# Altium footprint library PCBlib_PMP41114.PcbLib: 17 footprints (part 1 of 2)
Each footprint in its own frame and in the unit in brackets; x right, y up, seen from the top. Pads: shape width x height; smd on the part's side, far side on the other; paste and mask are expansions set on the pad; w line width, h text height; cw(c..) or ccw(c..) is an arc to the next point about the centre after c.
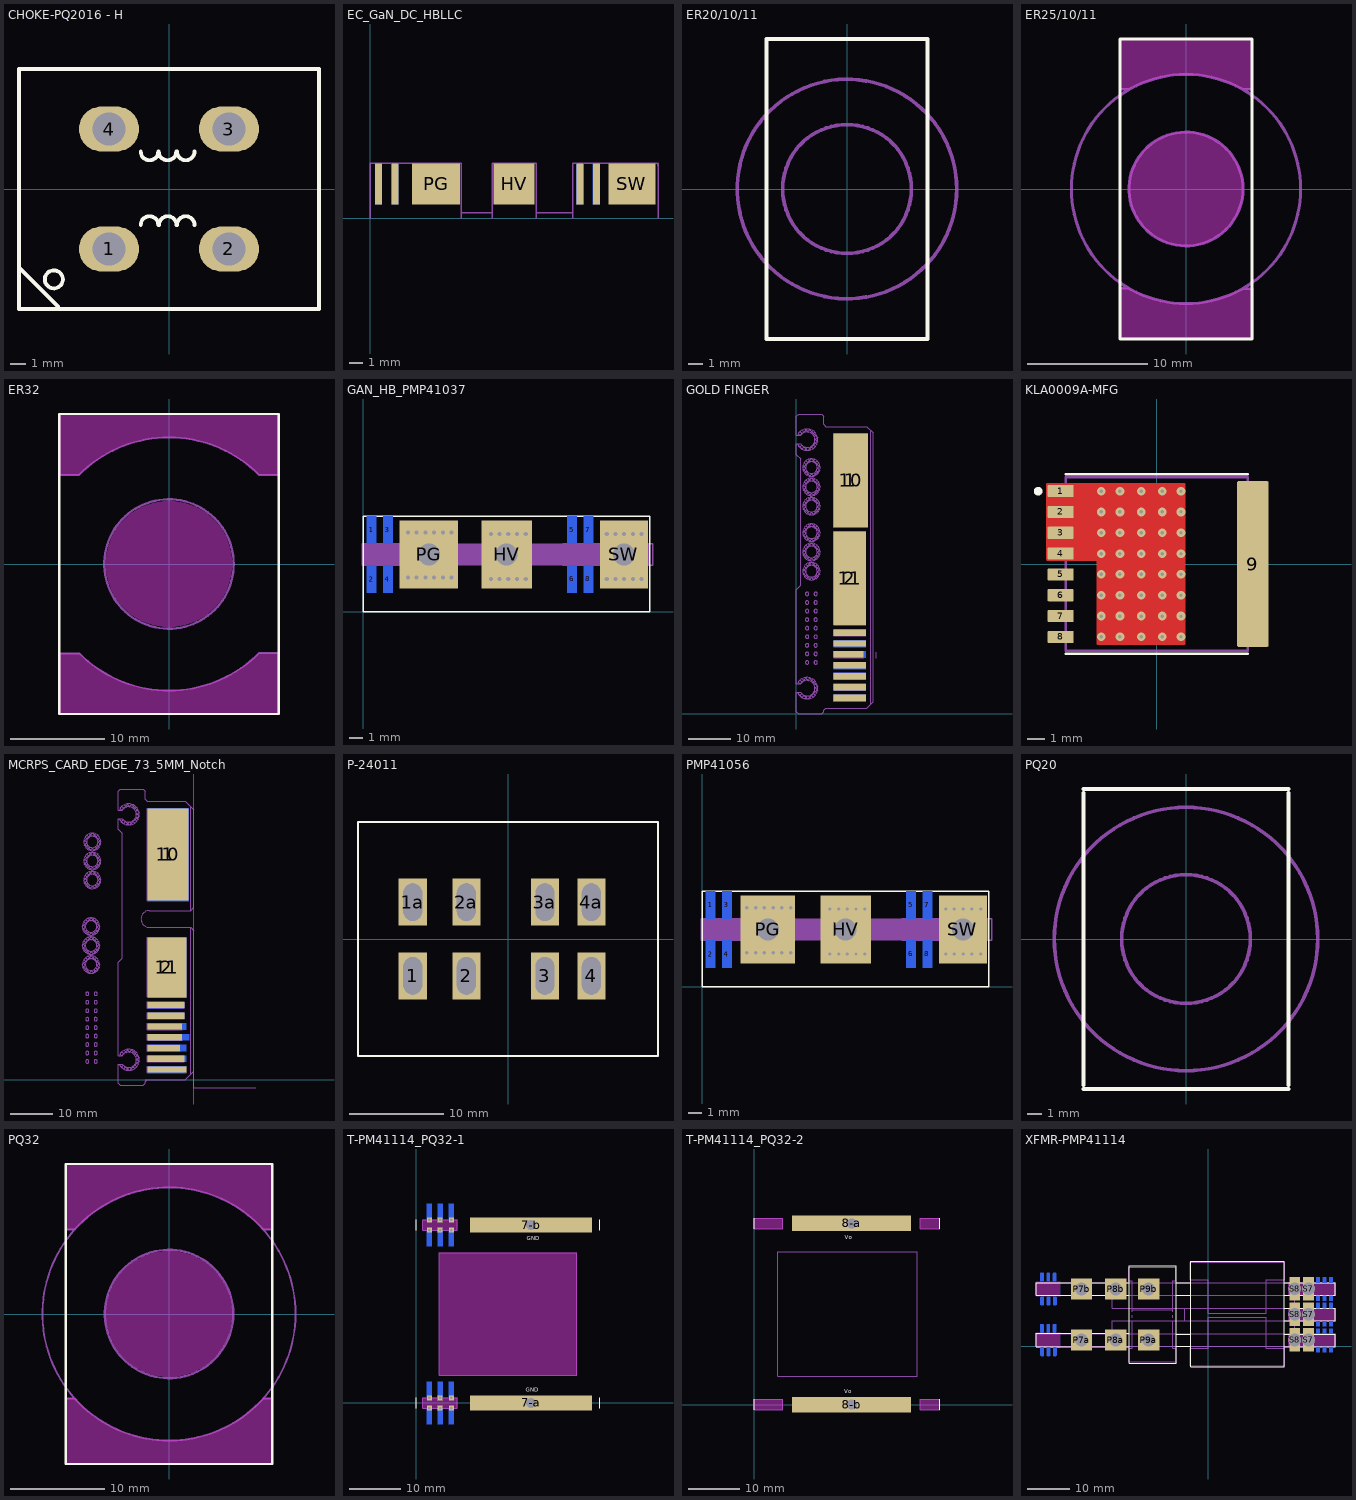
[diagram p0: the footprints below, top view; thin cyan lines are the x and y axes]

## CHOKE-PQ2016 - H [mm]
pads (4):
  oval 4x3 hole 2.2: 1(-4,-4) 2(4,-4) 3(4,4) 4(-4,4)
Top Overlay:
  circle w0.254: c-7.677,-6.026 r0.6
  lines w0.254: -10,-8 10,-8 ; -10,8 10,8 ; -9.906,-5.334 -7.406,-7.834 ; -1.883,-2.4 cw(c-1.3,-2.4) -0.717,-2.4 ; -1.883,2.5 ccw(c-1.3,2.5) -0.717,2.5 ; -0.683,2.5 ccw(c-0.1,2.5) 0.483,2.5 ; -0.666,-2.4 cw(c-0.083,-2.4) 0.5,-2.4 ; 0.534,-2.4 cw(c1.117,-2.4) 1.7,-2.4 ; 0.534,2.5 ccw(c1.117,2.5) 1.7,2.5
  lines w0.3: -10,-8 -10,8 ; 10,-8 10,8

## EC_GaN_DC_HBLLC [mm] "Edge connector of HB LLC GaN DC"
height 0.7
pads (11):
  rect 0.5x3 smd: 1(0.6,2.5) 3(1.8,2.5) 5(15.3,2.5) 7(16.5,2.5)
  rect 0.5x3 smd far side: 2(0.6,2.5) 4(1.8,2.5) 6(15.3,2.5) 8(16.5,2.5)
  rect 3x3 all layers, no hole: HV(10.5,2.5)
  rect 3.5x3 all layers, no hole: PG(4.8,2.5)
  rect 3.4x3 all layers, no hole: SW(19.1,2.5)
Mechanical 1:
  lines w0.1: -0.005,4 6.649,4 6.649,0.4 8.91,0.4 8.91,4 12.11,4 12.11,0.4 14.777,0.4 14.777,4 20.995,4 20.995,3.835
Mechanical 12:
  lines w0.1: 0,0 0,4 6.649,4 6.649,0 ; 8.9,0 8.9,4 12.1,4 12.1,0 ; 14.787,0 14.787,4 21,4 21,0

## ER20/10/11 [mm]
Top Overlay:
  lines w0.254: -5.5,-10.25 5.5,-10.25 5.5,10.25 -5.5,10.25 -5.5,-10.25
Mechanical 15:
  circle w0.254: c0,0 r4.4
  circle w0.254: c0,0 r7.5

## ER25/10/11 [mm] "Core"
Top Overlay:
  lines w0.254: -5.5,-12.5 -5.5,12.5 5.5,12.5 5.5,-12.5 -5.5,-12.5
Keep-Out Layer:
  board cut-out: -5.5,8.3 -4.714,8.3 -4.714,8.306 -4.352,8.501 -3.604,8.844 -2.83,9.121 -2.035,9.331 -1.224,9.471 -0.405,9.541 0.417,9.541 1.236,9.47 2.047,9.328 2.842,9.117 3.615,8.839 4.362,8.495 4.724,8.3 4.8,8.3 5.5,8.3 5.5,12.5 -5.5,12.5
  board cut-out: -5.493,-12.493 5.531,-12.493 5.531,-8.297 4.728,-8.297 4.363,-8.495 3.609,-8.842 2.828,-9.122 2.025,-9.333 1.207,-9.473 0.379,-9.542 -0.451,-9.539 -1.277,-9.464 -2.094,-9.317 -2.896,-9.1 -3.675,-8.815 -4.427,-8.462 -4.79,-8.262 -4.8,-8.278 -5.493,-8.278
  board cut-out: 0,-4.75 -0.311,-4.75 -0.929,-4.669 -1.53,-4.508 -2.105,-4.269 -2.645,-3.958 -3.139,-3.579 -3.579,-3.139 -3.958,-2.645 -4.269,-2.105 -4.508,-1.53 -4.669,-0.929 -4.75,-0.311 -4.75,0 -4.75,0.311 -4.669,0.929 -4.508,1.53 -4.269,2.105 -3.958,2.645 -3.579,3.139 -3.139,3.579 -2.645,3.958 -2.105,4.269 -1.53,4.508 -0.929,4.669 -0.311,4.75 0,4.75 0.311,4.75 0.929,4.669 1.53,4.508 2.105,4.269 2.645,3.958 3.139,3.579 3.579,3.139 3.958,2.645 4.269,2.105 4.508,1.53 4.669,0.929 4.75,0.311 4.75,0 4.75,-0.311 4.669,-0.929 4.508,-1.53 4.269,-2.105 3.958,-2.645 3.579,-3.139 3.139,-3.579 2.645,-3.958 2.105,-4.269 1.53,-4.508 0.929,-4.669 0.311,-4.75
Mechanical 2:
  circle w0.254: c0,0 r9.55
  circle w0.254: c0,0 r4.75
  lines w0.2: -5.5,-8.278 -4.8,-8.278 ; -5.493,-8.278 -5.493,-12.493 5.531,-12.493 5.531,-8.297 ; -4.79,-8.262 ccw(c0,0) 4.728,-8.297 5.5,-8.297 ; -4.714,8.3 -5.5,8.3 -5.5,12.5 5.5,12.5 5.5,8.3 4.8,8.3 ; -4.714,8.306 cw(c0,0) 4.724,8.3
3D body: height 0.25, standoff 0, extent -5.5,-12.5 5.5,12.5

## ER32 [mm] "Compatible to PQ32"
Top Overlay:
  lines w0.254: -11.7,-16 11.7,-16 11.7,16 -11.7,16 -11.7,-16
Keep-Out Layer:
  board cut-out: 0,-6.725 -0.33,-6.725 -0.988,-6.66 -1.636,-6.531 -2.268,-6.34 -2.879,-6.087 -3.462,-5.775 -4.011,-5.408 -4.522,-4.989 -4.989,-4.522 -5.408,-4.011 -5.775,-3.462 -6.087,-2.879 -6.34,-2.268 -6.531,-1.636 -6.66,-0.988 -6.725,-0.33 -6.725,0 -6.725,0.33 -6.66,0.988 -6.531,1.636 -6.34,2.268 -6.087,2.879 -5.775,3.462 -5.408,4.011 -4.989,4.522 -4.522,4.989 -4.011,5.408 -3.462,5.775 -2.879,6.087 -2.268,6.34 -1.636,6.531 -0.988,6.66 -0.33,6.725 0,6.725 0.33,6.725 0.988,6.66 1.636,6.531 2.268,6.34 2.879,6.087 3.462,5.775 4.011,5.408 4.522,4.989 4.989,4.522 5.408,4.011 5.775,3.462 6.087,2.879 6.34,2.268 6.531,1.636 6.66,0.988 6.725,0.33 6.725,0 6.725,-0.33 6.66,-0.988 6.531,-1.636 6.34,-2.268 6.087,-2.879 5.775,-3.462 5.408,-4.011 4.989,-4.522 4.522,-4.989 4.011,-5.408 3.462,-5.775 2.879,-6.087 2.268,-6.34 1.636,-6.531 0.988,-6.66 0.33,-6.725
  board cut-out: -11.7,9.5 -9.6,9.5 -9.596,9.496 -9.213,9.868 -8.405,10.564 -7.544,11.195 -6.636,11.756 -5.687,12.244 -4.702,12.655 -3.688,12.986 -2.651,13.237 -1.597,13.405 -0.534,13.489 0.534,13.489 1.597,13.405 2.651,13.237 3.688,12.986 4.702,12.655 5.687,12.244 6.636,11.756 7.544,11.195 8.405,10.564 9.213,9.868 9.596,9.496 9.6,9.5 11.7,9.5 11.7,16 -11.7,16
  board cut-out: -11.7,-16 -11.7,-9.542 -9.6,-9.542 -9.575,-9.517 -9.192,-9.888 -8.383,-10.582 -7.522,-11.21 -6.615,-11.768 -5.666,-12.253 -4.682,-12.662 -3.669,-12.992 -2.633,-13.241 -1.58,-13.407 -0.518,-13.49 0.548,-13.489 1.61,-13.404 2.662,-13.235 3.698,-12.984 4.71,-12.652 5.693,-12.241 6.641,-11.754 7.547,-11.193 8.407,-10.563 9.214,-9.867 9.596,-9.496 9.6,-9.5 11.7,-9.5 11.7,-16
Mechanical 2:
  circle w0.254: c0,0 r6.9
  lines w0.2: -9.6,-9.542 -11.7,-9.542 -11.7,-16 11.7,-16 11.7,-9.5 9.6,-9.5 ; -9.6,9.5 -11.7,9.5 -11.7,16 11.7,16 11.7,9.5 9.6,9.5 ; -9.596,9.496 cw(c0,0) 9.596,9.496 ; -9.575,-9.517 ccw(c0,0) 9.596,-9.496
3D body: height 0.25, standoff 0, extent -11.048,-15.968 11,16

## GAN_HB_PMP41037 [mm]
height 32
pads (11):
  rect 0.7x2 smd far side: 1(0.6,6) 2(0.6,2.4) 3(1.8,6) 4(1.8,2.4) 5(15.3,6) 6(15.3,2.4) 7(16.5,6) 8(16.5,2.4)
  rect 3.7x5 hole 1.6 square: HV(10.5,4.2)
  rect 4.3x5 hole 1.6 square: PG(4.8,4.2)
  rect 3.5x5 hole 1.6 square: SW(19.1,4.2)
via 3.9,2.5 diameter 0.5 hole 0.3
via 4.54,2.5 diameter 0.5 hole 0.3
via 5.18,2.5 diameter 0.5 hole 0.3
via 5.82,2.5 diameter 0.5 hole 0.3
via 6.46,2.5 diameter 0.5 hole 0.3
via 6.46,5.8 diameter 0.5 hole 0.3
via 5.82,5.8 diameter 0.5 hole 0.3
via 5.18,5.8 diameter 0.5 hole 0.3
via 4.54,5.8 diameter 0.5 hole 0.3
via 3.9,5.8 diameter 0.5 hole 0.3
via 9.34,2.4 diameter 0.5 hole 0.3
via 9.98,2.4 diameter 0.5 hole 0.3
via 10.62,2.4 diameter 0.5 hole 0.3
via 11.26,2.4 diameter 0.5 hole 0.3
via 11.9,2.4 diameter 0.5 hole 0.3
via 11.9,5.7 diameter 0.5 hole 0.3
via 11.26,5.7 diameter 0.5 hole 0.3
via 10.62,5.7 diameter 0.5 hole 0.3
via 9.98,5.7 diameter 0.5 hole 0.3
via 9.34,5.7 diameter 0.5 hole 0.3
via 17.84,2.4 diameter 0.5 hole 0.3
via 18.48,2.4 diameter 0.5 hole 0.3
via 19.12,2.4 diameter 0.5 hole 0.3
via 19.76,2.4 diameter 0.5 hole 0.3
via 20.4,2.4 diameter 0.5 hole 0.3
via 20.4,5.7 diameter 0.5 hole 0.3
via 19.76,5.7 diameter 0.5 hole 0.3
via 19.12,5.7 diameter 0.5 hole 0.3
via 18.48,5.7 diameter 0.5 hole 0.3
via 17.84,5.7 diameter 0.5 hole 0.3
via 3.26,5.8 diameter 0.5 hole 0.3
via 3.26,2.5 diameter 0.5 hole 0.3
Top Overlay:
  lines w0.1: 0,0 21,0 21,7 0,7 0,0
Mechanical 1:
  lines w0.1: -0.1,3.4 -0.1,5 6.8,5 6.8,3.4 -0.1,3.4 ; 8.763,3.4 12.246,3.4 12.246,5 8.763,5 8.763,3.4 ; 14.6,3.4 14.6,5 21.2,5 21.2,3.4 14.6,3.4
Mechanical 2:
  rectangle: 0,3.4 21,5
3D body: height 32, standoff 0, extent -0.1,3.4 21.2,5

## GOLD FINGER [mm]
pads (18):
  rect 8x21.83 smd: 1(12.748,54.51)
  rect 7.5x21.82 smd: 2(12.498,31.65)
  rect 7.5x1.5 smd: 3(12.498,18.96) 4(12.498,16.42) 6(12.498,11.34) 7(12.498,8.8) 8(12.498,6.26) 9(12.498,3.72)
  rect 7x1.5 smd: 5(12.248,13.88)
  rect 8x21.83 smd far side: 10(12.748,54.51)
  rect 7.5x21.82 smd far side: 11(12.498,31.65)
  rect 7.5x1.5 smd far side: 12(12.498,18.96) 13(12.498,16.42) 14(12.498,13.88) 15(12.498,11.34) 16(12.498,8.8) 17(12.498,6.26) 18(12.498,3.72)
Mechanical 16:
  drawing of 327 lines, arcs and shapes, not listed

## KLA0009A-MFG [mm]
height 16
pads (9):
  rrect14% 1.5x0.7 smd paste+0 mask-1000: 1(-5.539,4.2) 2(-5.539,3) 3(-5.539,1.8) 4(-5.539,0.6) 5(-5.539,-0.6) 6(-5.539,-1.8) 7(-5.539,-3) 8(-5.539,-4.2)
  rrect15% 1.843x9.6 smd paste-1000 mask-1000: 9(5.539,0)
via -3.208,4.2 diameter 0.5 hole 0.2
via -3.208,3 diameter 0.5 hole 0.2
via -3.208,1.8 diameter 0.5 hole 0.2
via -3.208,0.6 diameter 0.5 hole 0.2
via -3.208,-0.6 diameter 0.5 hole 0.2
via -3.208,-1.8 diameter 0.5 hole 0.2
via -3.208,-3 diameter 0.5 hole 0.2
via -3.208,-4.2 diameter 0.5 hole 0.2
via -2.12,4.2 diameter 0.5 hole 0.2
via -2.12,3 diameter 0.5 hole 0.2
via -2.12,1.8 diameter 0.5 hole 0.2
via -2.12,0.6 diameter 0.5 hole 0.2
via -2.12,-0.6 diameter 0.5 hole 0.2
via -2.12,-1.8 diameter 0.5 hole 0.2
via -2.12,-3 diameter 0.5 hole 0.2
via -2.12,-4.2 diameter 0.5 hole 0.2
via -0.9,4.2 diameter 0.5 hole 0.2
via -0.9,3 diameter 0.5 hole 0.2
via -0.9,1.8 diameter 0.5 hole 0.2
via -0.9,0.6 diameter 0.5 hole 0.2
via -0.9,-0.6 diameter 0.5 hole 0.2
via -0.9,-1.8 diameter 0.5 hole 0.2
via -0.9,-3 diameter 0.5 hole 0.2
via -0.9,-4.2 diameter 0.5 hole 0.2
via 0.32,4.2 diameter 0.5 hole 0.2
via 0.32,3 diameter 0.5 hole 0.2
via 0.32,1.8 diameter 0.5 hole 0.2
via 0.32,0.6 diameter 0.5 hole 0.2
via 0.32,-0.6 diameter 0.5 hole 0.2
via 0.32,-1.8 diameter 0.5 hole 0.2
via 0.32,-3 diameter 0.5 hole 0.2
via 0.32,-4.2 diameter 0.5 hole 0.2
via 1.4,4.2 diameter 0.5 hole 0.2
via 1.4,3 diameter 0.5 hole 0.2
via 1.4,1.8 diameter 0.5 hole 0.2
via 1.4,0.6 diameter 0.5 hole 0.2
via 1.4,-0.6 diameter 0.5 hole 0.2
via 1.4,-1.8 diameter 0.5 hole 0.2
via 1.4,-3 diameter 0.5 hole 0.2
via 1.4,-4.2 diameter 0.5 hole 0.2
Top Layer:
  region: -6.36,4.6 -6.36,4.614 -6.349,4.64 -6.33,4.659 -6.304,4.67 -6.29,4.67 1.587,4.67 1.601,4.67 1.627,4.659 1.646,4.64 1.657,4.614 1.657,4.6 1.657,-4.6 1.657,-4.614 1.646,-4.64 1.627,-4.659 1.601,-4.67 1.587,-4.67 -3.388,-4.67 -3.402,-4.67 -3.428,-4.659 -3.447,-4.64 -3.458,-4.614 -3.458,-4.6 -3.458,0.13 -3.459,0.14 -3.466,0.158 -3.48,0.172 -3.498,0.179 -3.508,0.18 -6.29,0.18 -6.304,0.18 -6.33,0.191 -6.349,0.21 -6.36,0.236 -6.36,0.25
Top Overlay:
  circle w0.25: c-6.837,4.197 r0.125
  lines w0.15: -5.24,-5.175 5.24,-5.175 ; -5.24,5.175 5.24,5.175
Top Paste:
  drawing of 40 lines, arcs and shapes, not listed
Top Solder:
  drawing of 6 lines, arcs and shapes, not listed
Mechanical 5:
  lines w0.15: -5.24,-5 -5.24,5 5.24,5 5.24,-5 -5.24,-5
  text ".Designator" at 0.733,-0.083 h0.5
3D body "IC_LMG365x_TO-9.STEP": height 0.25, standoff 0, extent -6.46,-5.1 6.56,5.1

## MCRPS_CARD_EDGE_73_5MM_Notch [mm] "Edge Connector with golden finger"
pads (18):
  rect 9.75x21.83 smd: 1(-6.1,53.2)
  rect 9.25x14.2 smd: 2(-6.369,26.52)
  rect 8.75x1.5 smd: 3(-6.625,17.63) 4(-6.625,15.09) 8(-6.625,4.93)
  rect 8.25x1.5 smd: 5(-6.875,12.55) 6(-6.875,10.01)
  rect 7.75x1.5 smd: 7(-7.125,7.47)
  rect 9.25x1.5 smd: 9(-6.375,2.39)
  rect 9.75x21.83 smd far side: 10(-6.125,53.19)
  rect 9.25x14.2 smd far side: 11(-6.375,26.52)
  rect 8.75x1.5 smd far side: 12(-6.625,17.63) 13(-6.625,15.09) 18(-6.625,2.39)
  rect 9.25x1.5 smd far side: 14(-6.375,12.55) 16(-6.375,7.47) 17(-6.375,4.93)
  rect 9.9x1.5 smd far side: 15(-6.05,10.01)
Mechanical 10:
  lines w0.025: 0,2 0,-1.9 14.6,-1.9
  text "30u in GOLD  /100u in NICKEL" at 1.648,16.052 h0.76
  text "2x 0.77mm, 2x 30 deg" at 1.452,-1.494 h0.76
Mechanical 15:
  drawing of 329 lines, arcs and shapes, not listed
Mechanical 16:
  drawing of 325 lines, arcs and shapes, not listed

## P-24011 [mm] "LLC transformer from Cyntec"
pads (8):
  rect 3x5 hole 2 slot 4 at 90 deg: 1(-10.16,-3.937) 1a(-10.16,3.937) 2(-4.445,-3.937) 2a(-4.445,3.937) 3(3.937,-3.937) 3a(3.937,3.937) 4(8.89,-3.937) 4a(8.89,3.937)
Top Overlay:
  lines w0.2: -16,-12.5 -16,12.5 16,12.5 16,-12.5 -16,-12.5

## PMP41056 [mm] "GaN board Interface"
height 32
pads (11):
  rect 0.7x2 smd far side: 1(0.6,6) 2(0.6,2.4) 3(1.8,6) 4(1.8,2.4) 5(15.3,6) 6(15.3,2.4) 7(16.5,6) 8(16.5,2.4)
  rect 3.7x5 hole 1.6 square: HV(10.5,4.2)
  rect 4x5 hole 1.6 square: PG(4.8,4.2)
  rect 3.5x5 hole 1.6 square: SW(19.1,4.2)
via 3.26,2.5 diameter 0.5 hole 0.254
via 3.26,5.8 diameter 0.5 hole 0.254
via 17.84,5.7 diameter 0.5 hole 0.254
via 18.48,5.7 diameter 0.5 hole 0.254
via 19.12,5.7 diameter 0.5 hole 0.254
via 19.76,5.7 diameter 0.5 hole 0.254
via 20.4,5.7 diameter 0.5 hole 0.254
via 20.4,2.4 diameter 0.5 hole 0.254
via 19.76,2.4 diameter 0.5 hole 0.254
via 19.12,2.4 diameter 0.5 hole 0.254
via 18.48,2.4 diameter 0.5 hole 0.254
via 17.84,2.4 diameter 0.5 hole 0.254
via 9.34,5.7 diameter 0.5 hole 0.254
via 9.98,5.7 diameter 0.5 hole 0.254
via 10.62,5.7 diameter 0.5 hole 0.254
via 11.26,5.7 diameter 0.5 hole 0.254
via 11.9,5.7 diameter 0.5 hole 0.254
via 11.9,2.4 diameter 0.5 hole 0.254
via 11.26,2.4 diameter 0.5 hole 0.254
via 10.62,2.4 diameter 0.5 hole 0.254
via 9.98,2.4 diameter 0.5 hole 0.254
via 9.34,2.4 diameter 0.5 hole 0.254
via 3.9,5.8 diameter 0.5 hole 0.254
via 4.54,5.8 diameter 0.5 hole 0.254
via 5.18,5.8 diameter 0.5 hole 0.254
via 5.82,5.8 diameter 0.5 hole 0.254
via 6.46,5.8 diameter 0.5 hole 0.254
via 6.46,2.5 diameter 0.5 hole 0.254
via 5.82,2.5 diameter 0.5 hole 0.254
via 5.18,2.5 diameter 0.5 hole 0.254
via 4.54,2.5 diameter 0.5 hole 0.254
via 3.9,2.5 diameter 0.5 hole 0.254
Top Overlay:
  lines w0.1: 0,0 0,7 21,7 21,0 0,0
Mechanical 1:
  lines w0.1: -0.1,3.4 6.8,3.4 6.8,5 -0.1,5 -0.1,3.4 ; 8.763,3.4 8.763,5 12.246,5 12.246,3.4 8.763,3.4 ; 14.6,3.4 21.2,3.4 21.2,5 14.6,5 14.6,3.4
Mechanical 2:
  rectangle: 0,3.4 21,5

## PQ20 [mm] "Core"
Top Overlay:
  lines w0.254: -7,-10.25 7,-10.25 ; -7,-10 -7,10 ; -7,10.25 7,10.25 ; 7,-10 7,10
Mechanical 2:
  circle w0.254: c0,0 r4.4
  circle w0.254: c0,0 r9

## PQ32 [mm] "Core"
Top Overlay:
  lines w0.254: -11,-16 11,-16 11,16 -11,16 -11,-16
Keep-Out Layer:
  board cut-out: 0,-6.725 -0.33,-6.725 -0.988,-6.66 -1.636,-6.531 -2.268,-6.34 -2.879,-6.087 -3.462,-5.775 -4.011,-5.408 -4.522,-4.989 -4.989,-4.522 -5.408,-4.011 -5.775,-3.462 -6.087,-2.879 -6.34,-2.268 -6.531,-1.636 -6.66,-0.988 -6.725,-0.33 -6.725,0 -6.725,0.33 -6.66,0.988 -6.531,1.636 -6.34,2.268 -6.087,2.879 -5.775,3.462 -5.408,4.011 -4.989,4.522 -4.522,4.989 -4.011,5.408 -3.462,5.775 -2.879,6.087 -2.268,6.34 -1.636,6.531 -0.988,6.66 -0.33,6.725 0,6.725 0.33,6.725 0.988,6.66 1.636,6.531 2.268,6.34 2.879,6.087 3.462,5.775 4.011,5.408 4.522,4.989 4.989,4.522 5.408,4.011 5.775,3.462 6.087,2.879 6.34,2.268 6.531,1.636 6.66,0.988 6.725,0.33 6.725,0 6.725,-0.33 6.66,-0.988 6.531,-1.636 6.34,-2.268 6.087,-2.879 5.775,-3.462 5.408,-4.011 4.989,-4.522 4.522,-4.989 4.011,-5.408 3.462,-5.775 2.879,-6.087 2.268,-6.34 1.636,-6.531 0.988,-6.66 0.33,-6.725
  board cut-out: -11,-16 -11,-9 -10.062,-9 -9.676,-9.415 -8.851,-10.193 -7.965,-10.9 -7.022,-11.53 -6.03,-12.079 -4.995,-12.542 -3.925,-12.917 -2.827,-13.201 -1.71,-13.391 -0.58,-13.488 0.554,-13.489 1.684,-13.395 2.802,-13.206 3.9,-12.924 4.971,-12.552 6.006,-12.09 7,-11.544 7.943,-10.916 8.831,-10.211 9.657,-9.434 10.045,-9.02 10.045,-9 11,-9 11,-16
  board cut-out: -11,9 -11,16 11,16 11,9 10.045,9 10.062,9 9.676,9.415 8.851,10.193 7.965,10.9 7.022,11.53 6.03,12.079 4.995,12.542 3.925,12.917 2.827,13.201 1.71,13.391 0.58,13.488 -0.554,13.489 -1.684,13.395 -2.802,13.206 -3.9,12.924 -4.971,12.552 -6.006,12.09 -7,11.544 -7.943,10.916 -8.831,10.211 -9.657,9.434 -10.045,9.02 -10.045,9
Mechanical 2:
  circle w0.2: c0,0 r13.5
  circle w0.254: c0,0 r6.85
  lines w0.2: -10.045,9 -11,9 -11,16 11,16 11,9 10.045,9 ; -10.045,9.02 cw(c0,0) 10.062,9 ; 10.045,-9.02 cw(c0,0) -10.062,-9 -11,-9 -11,-16 11,-16 11,-9 10.045,-9
3D body: height 0.25, standoff 0, extent -11.048,-15.968 11,16

## T-PM41114_PQ32-1 [mm] "Customized to Sunlord"
pads (26):
  rect 1x3 smd far side: 1-a(2.545,-2.7) 1-b(2.545,32.3) 2-a(4.65,-2.7) 2-b(4.65,32.3) 3-a(6.85,-2.7) 3-b(6.85,32.3) 4-a(2.545,2.7) 4-b(2.545,37.7) 5-a(4.65,2.7) 5-b(4.65,37.7) 6-a(6.85,2.7) 6-b(6.85,37.7)
  rect 1x1 hole 0.5: 1-a(2.545,-1) 1-b(2.545,34) 2-a(4.65,-1) 2-b(4.65,34) 3-a(6.85,-1) 3-b(6.85,34) 4-a(2.545,1) 4-b(2.545,36) 5-a(4.65,1) 5-b(4.65,36) 6-a(6.85,1) 6-b(6.85,36)
  rect 24x3 hole 2 square: 7-a(22.55,0) 7-b(22.55,35)
Top Overlay:
  lines w0.2: 0,-1 0,1 ; 0,34 0,36 ; 36,-1 36,1 ; 36,34 36,36
  text "GND" at 21.452,2.252 h0.76
  text "GND" at 21.652,32.052 h0.76
Keep-Out Layer:
  board cut-out: 4.5,5.5 4.5,29.5 31.5,29.5 31.5,5.5
  board cut-out: 1.2,-1 8,-1 8,1 1.2,1
  board cut-out: 1.2,34 8,34 8,36 1.2,36
Mechanical 1:
  lines w0.2: 1.2,-1 1.2,1 ; 1.2,-1 8,-1 ; 1.2,-1 1.2,1 ; 1.2,-1 8,-1 ; 1.2,1 8,1 ; 1.2,1 8,1 ; 8,-1 8,1 ; 8,-1 8,1 ; 1.2,34 1.2,36 8,36 8,34 1.2,34 ; 4.5,5.5 4.5,29.5 31.5,29.5 31.5,5.5 4.5,5.5
3D body: height 27.5, standoff -4.5, extent 4.5,5.5 31.5,29.5
3D body: height 30, standoff 0, extent 0,34 36,36
3D body: height 30, standoff 0, extent 0,-1 36,1

## T-PM41114_PQ32-2 [mm]
pads (2):
  rect 23x3 hole 2 square: 8-a(18.8,35) 8-b(18.8,0)
Top Overlay:
  lines w0.2: 0,-1 0,1 ; 0,34 0,36 ; 35.8,-1 35.8,1 ; 35.8,34 35.8,36
  text "Vo" at 17.352,2.152 h0.76
  text "Vo" at 17.452,31.952 h0.76
Keep-Out Layer:
  board cut-out: 0,-1 5.5,-1 5.5,1 0,1
  board cut-out: 0,34 5.5,34 5.5,36 0,36
  board cut-out: 35.8,36 32.1,36 32.1,34 35.8,34
  board cut-out: 35.8,1 32.1,1 32.1,-1 35.8,-1
Mechanical 1:
  lines w0.2: 0,-1 0,1 5.5,1 5.5,-1 0,-1 ; 0,34 0,36 5.5,36 5.5,34 0,34 ; 4.5,5.5 4.5,29.5 31.5,29.5 31.5,5.5 4.5,5.5 ; 32.1,-1 35.8,-1 35.8,1 32.1,1 32.1,-1 ; 32.1,34 35.8,34 35.8,36 32.1,36 32.1,34
3D body: height 32, standoff 0, extent 4.5,5.5 31.5,29.5
3D body: height 30, standoff 0, extent 0,34 35.8,36
3D body: height 30, standoff 0, extent 0,-1 35.8,1

## XFMR-PMP41114 [mm]
pads (42):
  rrect50% 0.8x2 smd far side: P1a(-39.051,-1.249) P1b(-39.051,10.711) P2a(-39.103,4.251) P2b(-39.103,16.251) P3a(-37.551,-1.249) P3b(-37.551,10.711) P4a(-37.603,4.251) P4b(-37.603,16.251) P5a(-36.051,-1.249) P5b(-36.051,10.711) P6a(-36.103,4.251) P6b(-36.103,16.251)
  rect 5x5 hole 3 square: P7a(-29.8,1.5) P7b(-29.799,13.5) P8a(-21.783,1.5) P8b(-21.782,13.5) P9a(-14.053,1.5) P9b(-14.052,13.5)
  rect 0.8x1.2 smd far side: S1(28.748,-0.711) S1(28.748,5.3) S1(28.748,11.3) S2(28.748,3.589) S2(28.748,9.6) S2(28.748,15.6) S3(27.248,-0.711) S3(27.248,5.3) S3(27.248,11.3) S4(27.248,3.589) S4(27.248,9.6) S4(27.248,15.6) S5(25.748,-0.711) S5(25.748,5.3) S5(25.748,11.3) S6(25.748,3.589) S6(25.748,9.6) S6(25.748,15.6)
  rect 2.5x5.5 hole 3 square: S7(23.477,1.538) S7(23.477,7.549) S7(23.477,13.549) S8(20.237,1.538) S8(20.237,7.549) S8(20.237,13.549)
Top Overlay:
  lines w0.2: -18.711,11.989 -40.451,11.989 -40.451,14.989 -18.611,14.989 ; -18.7,3.108 -40.484,3.108 -40.484,-0.1 -18.6,-0.1 ; -7.6,0 -4.2,0 ; -7.6,2.9 -4.2,2.9 -4.2,5.9 ; -7.6,12 -4.2,12 ; -7.6,15 -4.2,15 ; -4.2,6 -4.2,9 ; 17.8,2.9 29.7,2.9 29.7,-0.1 17.9,-0.1 ; 17.8,9 29.7,9 29.7,6 17.9,6 ; 17.811,11.989 29.733,11.989 29.733,14.989 17.811,14.989
  lines w0.254: -18.6,-3.9 -7.6,-3.9 -7.6,18.89 -18.6,18.89 -18.6,-3.9 ; -4.2,-4.777 17.8,-4.777 17.8,20 -4.2,20 -4.2,-4.777
Keep-Out Layer:
  board cut-out: 18.783,12 18.783,15 29.933,15 29.933,12
  board cut-out: 18.783,6 18.783,9 29.933,9 29.933,6
  board cut-out: -40.466,11.8 -40.466,15.2 -34.816,15.2 -34.816,11.8
  board cut-out: 18.783,-0.011 18.783,2.989 29.933,2.989 29.933,-0.011
  board cut-out: -40.467,-0.2 -40.467,3.2 -34.817,3.2 -34.817,-0.2
Mechanical 2:
  lines w0.2: -40.467,-0.011 -40.467,2.989 ; -40.466,-0.011 29.734,-0.011 29.734,2.989 -40.466,2.989 ; -40.466,14.989 -40.466,11.989 29.734,11.989 29.734,15 -40.466,15 ; -22.634,2.989 -22.634,5.989 20.253,5.989 ; -22.634,11.989 -22.634,9 29.734,9 29.734,6 -5.55,6 -5.55,8.989 20.253,8.989 ; -9.55,2.989 20.253,2.989 ; 20.253,3 20.253,6 ; 20.253,9 20.253,12
Mechanical 15:
  lines w0.254: -18.661,-0.4 -17.911,-0.4 -17.911,6.077 ; -18.601,-0.397 -18.601,-3.597 -7.601,-3.597 -7.601,-0.397 ; -17.911,5.577 -17.911,6.077 ; -17.911,6.739 -17.911,7.327 ; -17.911,8.158 -17.911,8.577 ; -8.411,5.577 -8.411,6.077 ; -8.411,6.739 -8.411,7.327 ; -8.411,8.158 -8.411,8.577 ; -7.661,-0.4 -8.411,-0.4 -8.411,6.077 ; 17.85,-4.5 -4.3,-4.5 -4.3,-0.4 -0.025,-0.4 -0.025,6.827 13.575,6.827 13.575,-0.4 17.85,-0.4 17.85,-4.423 ; -17.911,6.077 -8.411,6.077 ; -17.911,8.577 -8.411,8.577 ; -17.911,8.577 -17.911,15.4 -18.661,15.4 -18.661,18.6 -7.661,18.6 -7.661,15.4 -8.411,15.4 -8.411,8.577 ; -4.3,15.6 -0.025,15.6 -0.025,7.827 13.575,7.827 13.575,15.6 17.85,15.6 17.85,19.7 -4.3,19.7 -4.3,15.6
